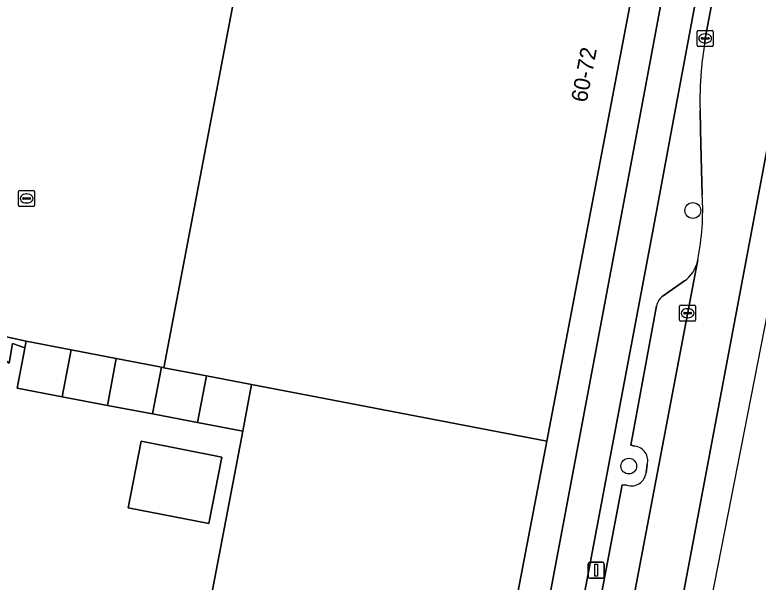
# Model space of a CAD drawing. Extents: x 161402 to 161933, y 381647 to 382315.
# Drawn here: x 161841.65 to 161887.93, y 381873.54 to 381908.84 of the extents above; entities that cross this region are included whole.
import ezdxf

# ---------------------------------------------------------------- set-up
doc = ezdxf.new("R2010")
doc.units = 0
for name, color, linetype in [('IMGEO_Boom', 7, 'Continuous'), ('IMGEO_Fietspad_gesloten', 7, 'Continuous'), ('IMGEO_Kolk', 7, 'Continuous'), ('IMGEO_Lichtmast', 7, 'Continuous'), ('IMGEO_Muur', 7, 'Continuous'), ('IMGEO_OVBaan_gesloten', 7, 'Continuous'), ('IMGEO_Pand', 7, 'Continuous'), ('IMGEO_Pand_nummerreeks', 7, 'Continuous'), ('IMGEO_Parkeervlak_open', 7, 'Continuous'), ('IMGEO_Rijbaan_lokaal_gesloten', 7, 'Continuous'), ('IMGEO_Verkeerseiland_open', 7, 'Continuous'), ('IMGEO_Voetpad_open', 7, 'Continuous')]:
    doc.layers.add(name, color=color, linetype=linetype)

msp = doc.modelspace()

# ---------------------------------------------------------------- linework, layer by layer
at = {"layer": 'IMGEO_Boom'}
for centre in [(161883.862, 381896.668), (161879.874, 381880.763)]:
    msp.add_circle(centre, 0.489, dxfattribs=at)
at = {"layer": 'IMGEO_Fietspad_gesloten'}
for points in [[(161910.061, 382061.001), (161905.702, 382037.375), (161898.752, 382000), (161887.89, 381941.593), (161886.669, 381935.154), (161880.56, 381902.497), (161879.486, 381896.758), (161857.65, 381780.798), (161851.928, 381750), (161842.232, 381697.819)], [(161881.54, 381896.271), (161882.623, 381902.093), (161888.398, 381933.147), (161890.059, 381942.083), (161900.83, 382000), (161908.061, 382038.88), (161912.039, 382060.567)], [(161844.249, 381697.445), (161849.541, 381725.922), (161850.643, 381731.85), (161854.016, 381750), (161859.509, 381779.56), (161864.254, 381804.698), (161864.714, 381807.133), (161867.323, 381820.954), (161867.824, 381823.608), (161869.899, 381834.602), (161881.54, 381896.271)]]:
    msp.add_lwpolyline(points, dxfattribs=at)
at = {"layer": 'IMGEO_Kolk'}
for p, q in [((161884.132, 381906.949), (161884.132, 381907.801)), ((161884.207, 381907.875), (161885.059, 381907.875)), ((161885.133, 381907.801), (161885.133, 381906.949)), ((161884.391, 381907.369), (161884.391, 381907.381)), ((161884.829, 381907.332), (161884.431, 381907.332)), ((161884.434, 381907.418), (161884.832, 381907.418)), ((161884.62, 381907.655), (161884.645, 381907.655)), ((161884.875, 381907.381), (161884.875, 381907.369)), ((161885.059, 381906.875), (161884.207, 381906.875)), ((161884.643, 381907.095), (161884.618, 381907.095)), ((161841.881, 381896.989), (161841.881, 381897.841)), ((161841.956, 381897.915), (161842.808, 381897.915)), ((161842.369, 381897.695), (161842.394, 381897.695)), ((161842.882, 381897.841), (161842.882, 381896.989)), ((161842.14, 381897.409), (161842.14, 381897.421)), ((161842.578, 381897.372), (161842.18, 381897.372)), ((161842.183, 381897.458), (161842.581, 381897.458)), ((161842.392, 381897.135), (161842.367, 381897.135)), ((161842.624, 381897.421), (161842.624, 381897.409)), ((161842.808, 381896.915), (161841.956, 381896.915)), ((161883.036, 381889.853), (161883.036, 381890.705)), ((161883.111, 381890.779), (161883.963, 381890.779)), ((161884.037, 381890.705), (161884.037, 381889.853)), ((161883.295, 381890.273), (161883.295, 381890.285)), ((161883.733, 381890.236), (161883.335, 381890.236)), ((161883.338, 381890.322), (161883.736, 381890.322)), ((161883.524, 381890.559), (161883.549, 381890.559)), ((161883.779, 381890.285), (161883.779, 381890.273)), ((161883.963, 381889.779), (161883.111, 381889.779)), ((161883.547, 381889.999), (161883.522, 381889.999))]:
    msp.add_line(p, q, dxfattribs=at)
for points in [[(161884.132, 381906.949), (161884.132, 381907.801)], [(161884.207, 381907.875), (161885.059, 381907.875)], [(161885.133, 381907.801), (161885.133, 381906.949)], [(161885.059, 381906.875), (161884.207, 381906.875)], [(161841.881, 381896.989), (161841.881, 381897.841)], [(161841.956, 381897.915), (161842.808, 381897.915)], [(161842.882, 381897.841), (161842.882, 381896.989)], [(161842.808, 381896.915), (161841.956, 381896.915)], [(161883.036, 381889.853), (161883.036, 381890.705)], [(161883.111, 381890.779), (161883.963, 381890.779)], [(161884.037, 381890.705), (161884.037, 381889.853)], [(161883.963, 381889.779), (161883.111, 381889.779)]]:
    msp.add_lwpolyline(points, dxfattribs=at)
for centre, radius, start, end in [((161884.209, 381907.799), 0.0765, 91.552, 178.448), ((161884.209, 381907.799), 0.0765, 91.552, 178.448), ((161885.057, 381907.799), 0.0765, 1.552, 88.448), ((161885.057, 381907.799), 0.0765, 1.552, 88.448), ((161884.431, 381907.378), 0.0403, 85.8775, 175.7526), ((161884.428, 381907.368), 0.0366, 178.938, 274.7102), ((161884.832, 381907.375), 0.043, 264.8664, 352.4533), ((161884.836, 381907.38), 0.0386, 1.7309, 96.639), ((161884.209, 381906.951), 0.0765, 181.552, 268.448), ((161884.209, 381906.951), 0.0765, 181.552, 268.448), ((161885.057, 381906.951), 0.0765, 271.552, 358.448), ((161885.057, 381906.951), 0.0765, 271.552, 358.448), ((161841.958, 381897.839), 0.0765, 91.552, 178.448), ((161841.958, 381897.839), 0.0765, 91.552, 178.448), ((161842.806, 381897.839), 0.0765, 1.552, 88.448), ((161842.806, 381897.839), 0.0765, 1.552, 88.448), ((161842.18, 381897.418), 0.0403, 85.8775, 175.7526), ((161842.177, 381897.408), 0.0366, 178.938, 274.7102), ((161842.581, 381897.415), 0.043, 264.8664, 352.4533), ((161842.585, 381897.42), 0.0386, 1.7309, 96.639), ((161841.958, 381896.991), 0.0765, 181.552, 268.448), ((161841.958, 381896.991), 0.0765, 181.552, 268.448), ((161842.806, 381896.991), 0.0765, 271.552, 358.448), ((161842.806, 381896.991), 0.0765, 271.552, 358.448), ((161883.113, 381890.703), 0.0765, 91.552, 178.448), ((161883.113, 381890.703), 0.0765, 91.552, 178.448), ((161883.961, 381890.703), 0.0765, 1.552, 88.448), ((161883.961, 381890.703), 0.0765, 1.552, 88.448), ((161883.335, 381890.282), 0.0403, 85.8775, 175.7526), ((161883.332, 381890.272), 0.0366, 178.938, 274.7102), ((161883.736, 381890.279), 0.043, 264.8664, 352.4533), ((161883.74, 381890.284), 0.0386, 1.7309, 96.639), ((161883.113, 381889.855), 0.0765, 181.552, 268.448), ((161883.113, 381889.855), 0.0765, 181.552, 268.448), ((161883.961, 381889.855), 0.0765, 271.552, 358.448), ((161883.961, 381889.855), 0.0765, 271.552, 358.448)]:
    msp.add_arc(centre, radius, start, end, dxfattribs=at)
for centre, major_axis, ratio, start_param, end_param in [((161884.619, 381907.375), (-0.387, 0.002), 0.722429, 4.712389, 7.853982), ((161884.644, 381907.375), (-0.39, 0.002), 0.717154, 1.570796, 4.712389), ((161842.368, 381897.415), (-0.387, 0.002), 0.722429, 4.712389, 7.853982), ((161842.393, 381897.415), (-0.39, 0.002), 0.717154, 1.570796, 4.712389), ((161883.523, 381890.279), (-0.387, 0.002), 0.722429, 4.712389, 7.853982), ((161883.548, 381890.279), (-0.39, 0.002), 0.717154, 1.570796, 4.712389)]:
    msp.add_ellipse(centre, major_axis=major_axis, ratio=ratio, start_param=start_param, end_param=end_param, dxfattribs=at)
at = {"layer": 'IMGEO_Lichtmast'}
for p, q in [((161877.348, 381873.885), (161877.348, 381874.685)), ((161877.348, 381874.685), (161877.348, 381873.885)), ((161877.448, 381874.785), (161878.238, 381874.785)), ((161878.238, 381874.785), (161877.448, 381874.785)), ((161878.338, 381874.685), (161878.338, 381873.885)), ((161878.338, 381873.885), (161878.338, 381874.685)), ((161878.238, 381873.785), (161877.448, 381873.785)), ((161877.448, 381873.785), (161878.238, 381873.785))]:
    msp.add_line(p, q, dxfattribs=at)
msp.add_lwpolyline([(161877.768, 381874.66), (161877.918, 381874.66), (161877.918, 381873.91), (161877.768, 381873.91), (161877.768, 381874.66)], dxfattribs=at)
for centre, start, end in [((161877.448, 381874.685), 90, 180), ((161877.448, 381874.685), 90, 180), ((161878.238, 381874.685), 0, 90), ((161878.238, 381874.685), 360, 90), ((161877.448, 381873.885), 180, 270), ((161877.448, 381873.885), 180, 270), ((161878.238, 381873.885), 270, 0), ((161878.238, 381873.885), 270, 0)]:
    msp.add_arc(centre, 0.1, start, end, dxfattribs=at)
at = {"layer": 'IMGEO_Muur'}
msp.add_lwpolyline([(161842.271, 381888.132), (161842.348, 381888.535), (161839.967, 381889.053), (161835.006, 381892.594), (161834.817, 381891.606), (161839.754, 381888.208), (161841.29, 381887.172), (161841.509, 381888.382)], close=True, dxfattribs=at)
at = {"layer": 'IMGEO_OVBaan_gesloten'}
for points in [[(161847.327, 381677.629), (161847.814, 381679.325), (161869.795, 381786.79), (161883.773, 381866.122), (161911.481, 382007.357), (161916.93, 382035.129), (161933.101, 382124.399), (161931.462, 382125.963), (161930.949, 382121.39)], [(161929.574, 382113.249), (161927.659, 382104.365), (161926.989, 382101.276), (161926.695, 382099.95), (161920.797, 382074.121), (161920.568, 382072.989), (161920.066, 382070.485), (161894.174, 381930.698), (161894.155, 381930.593), (161893.956, 381929.536), (161893.492, 381927.072), (161889.963, 381908.334), (161866.208, 381782.197), (161866.199, 381782.149), (161865.069, 381776.053), (161864.537, 381773.18), (161864.311, 381771.961), (161856.328, 381728.885)]]:
    msp.add_lwpolyline(points, dxfattribs=at)
at = {"layer": 'IMGEO_Pand'}
for points in [[(161853.582, 381886.372), (161856.391, 381885.835), (161874.777, 381882.317), (161878.687, 381902.863), (161883.878, 381930.136), (161878.246, 381931.217), (161878.948, 381934.818), (161860.503, 381938.326), (161857.498, 381922.591), (161857.717, 381922.54), (161850.925, 381886.881)], [(161845.156, 381887.993), (161842.348, 381888.535), (161842.271, 381888.132), (161842.264, 381888.093), (161841.792, 381885.615), (161844.601, 381885.08)], [(161845.156, 381887.993), (161844.601, 381885.08), (161847.411, 381884.544), (161847.965, 381887.452)], [(161850.773, 381886.91), (161847.965, 381887.452), (161847.411, 381884.544), (161850.22, 381884.009)], [(161850.925, 381886.881), (161850.773, 381886.91), (161850.22, 381884.009), (161853.03, 381883.473), (161853.582, 381886.372)], [(161853.582, 381886.372), (161853.03, 381883.473), (161855.839, 381882.938), (161856.391, 381885.835)], [(161874.777, 381882.317), (161856.391, 381885.835), (161855.839, 381882.938), (161853.748, 381871.965), (161859.14, 381870.938), (161867.064, 381869.428), (161872.114, 381868.466)]]:
    msp.add_lwpolyline(points, close=True, dxfattribs=at)
at = {"layer": 'IMGEO_Parkeervlak_open'}
for points in [[(161857.717, 381922.54), (161857.498, 381922.591), (161851.702, 381923.695), (161851.911, 381924.831), (161854.619, 381939.456), (161854.463, 381939.508), (161852.77, 381930.725), (161842.669, 381932.702), (161835.006, 381892.594), (161839.967, 381889.053), (161842.348, 381888.535), (161845.156, 381887.993), (161847.965, 381887.452), (161850.773, 381886.91), (161850.925, 381886.881)], [(161853.724, 381877.185), (161848.702, 381878.177), (161849.518, 381882.31), (161854.54, 381881.318)], [(161853.724, 381877.185), (161854.54, 381881.318), (161849.518, 381882.31), (161848.702, 381878.177)]]:
    msp.add_lwpolyline(points, close=True, dxfattribs=at)
for points in [[(161865.316, 381804.498), (161860.529, 381779.475), (161861.521, 381781.789), (161862.376, 381783.945), (161863.081, 381785.029), (161863.613, 381786.178), (161864.093, 381787.863), (161884.15, 381893.504)], [(161883.334, 381892.284), (161882.019, 381891.364)], [(161881.594, 381890.733), (161879.995, 381882.07), (161880.247, 381882.004)], [(161853.748, 381871.965), (161855.839, 381882.938), (161853.03, 381883.473), (161850.22, 381884.009), (161847.411, 381884.544), (161844.601, 381885.08), (161841.792, 381885.615), (161842.264, 381888.093), (161842.271, 381888.132), (161841.509, 381888.382), (161841.29, 381887.172), (161839.754, 381888.208), (161839.201, 381885.271), (161838.65, 381882.342), (161838.099, 381879.413), (161837.548, 381876.485), (161836.997, 381873.556), (161836.446, 381870.628)], [(161881.019, 381880.86), (161880.948, 381880.353)], [(161879.762, 381879.577), (161879.458, 381879.605), (161877.266, 381867.994), (161876.563, 381864.27), (161876.505, 381863.965), (161876.827, 381863.931)]]:
    msp.add_lwpolyline(points, dxfattribs=at)
for centre, radius, start, end in [((161882.199, 381893.926), 1.996, 304.6546, 347.792), ((161882.645, 381890.484), 1.08, 125.4179, 166.6589), ((161880.157, 381881.111), 0.898, 343.7921, 84.2328), ((161880.039, 381880.448), 0.914, 252.3671, 354.0264)]:
    msp.add_arc(centre, radius, start, end, dxfattribs=at)
at = {"layer": 'IMGEO_Rijbaan_lokaal_gesloten'}
for points in [[(161891.107, 381941.989), (161889.505, 381933.058), (161889.483, 381932.953), (161889.257, 381931.885), (161886.857, 381919.088), (161884.634, 381907.375), (161884.615, 381907.144)], [(161866.208, 381782.197), (161889.963, 381908.334)], [(161884.315, 381902.888), (161884.344, 381901.757), (161884.369, 381900.783), (161884.448, 381897.633)], [(161884.17, 381893.607), (161884.15, 381893.504), (161864.093, 381787.863), (161863.613, 381786.178), (161863.081, 381785.029), (161862.376, 381783.945), (161861.521, 381781.789), (161860.529, 381779.475), (161860.503, 381779.34), (161859.554, 381774.178), (161858.781, 381770.01), (161857.682, 381764.091), (161856.164, 381755.911), (161855.069, 381750), (161851.669, 381731.66), (161850.569, 381725.731), (161845.879, 381700.449), (161845.656, 381699.227), (161845.077, 381696.29), (161841.891, 381681.821), (161841.621, 381680.659), (161841.162, 381678.679), (161840.43, 381675.643), (161840.392, 381675.483)]]:
    msp.add_lwpolyline(points, dxfattribs=at)
for centre, radius, start, end in [((161905.47, 381903.518), 21.168, 170.1369, 175.0841), ((161905.361, 381903.551), 21.056, 175.1484, 181.8047), ((161868.789, 381896.692), 15.687, 348.6598, 3.4401)]:
    msp.add_arc(centre, radius, start, end, dxfattribs=at)
at = {"layer": 'IMGEO_Verkeerseiland_open'}
for points in [[(161912.039, 382060.567), (161908.061, 382038.88), (161900.83, 382000), (161890.059, 381942.083), (161888.398, 381933.147), (161882.623, 381902.093), (161881.54, 381896.271), (161869.899, 381834.602), (161872.587, 381834.08), (161872.769, 381835.211)], [(161884.615, 381907.144), (161884.634, 381907.375), (161886.857, 381919.088), (161889.257, 381931.885), (161889.483, 381932.953), (161889.505, 381933.058), (161891.107, 381941.989)], [(161884.448, 381897.633), (161884.369, 381900.783), (161884.344, 381901.757), (161884.315, 381902.888)], [(161884.15, 381893.504), (161884.17, 381893.607)], [(161882.019, 381891.364), (161883.334, 381892.284)], [(161880.247, 381882.004), (161879.995, 381882.07), (161881.594, 381890.733)], [(161880.948, 381880.353), (161881.019, 381880.86)], [(161876.827, 381863.931), (161876.505, 381863.965), (161876.563, 381864.27), (161877.266, 381867.994), (161879.458, 381879.605), (161879.762, 381879.577)]]:
    msp.add_lwpolyline(points, dxfattribs=at)
for centre, radius, start, end in [((161905.47, 381903.518), 21.168, 170.1369, 175.0841), ((161905.361, 381903.551), 21.056, 175.1484, 181.8047), ((161868.789, 381896.692), 15.687, 348.6598, 3.4401), ((161882.199, 381893.926), 1.996, 304.6546, 347.792), ((161882.645, 381890.484), 1.08, 125.4179, 166.6589), ((161880.157, 381881.111), 0.898, 343.7921, 84.2328), ((161880.039, 381880.448), 0.914, 252.3671, 354.0264)]:
    msp.add_arc(centre, radius, start, end, dxfattribs=at)
at = {"layer": 'IMGEO_Voetpad_open'}
for points in [[(161884.914, 381936.489), (161883.878, 381930.136), (161878.687, 381902.863), (161874.777, 381882.317), (161872.114, 381868.466)], [(161879.486, 381896.758), (161880.56, 381902.497), (161886.669, 381935.154)], [(161842.232, 381697.819), (161851.928, 381750), (161857.65, 381780.798), (161879.486, 381896.758)]]:
    msp.add_lwpolyline(points, dxfattribs=at)

# ---------------------------------------------------------------- texts
at = {"layer": 'IMGEO_Pand_nummerreeks'}
msp.add_text('60-72', height=1, rotation=79.2235, dxfattribs=at).set_placement((161877.253, 381903.35))

doc.saveas('drawing.dxf')
